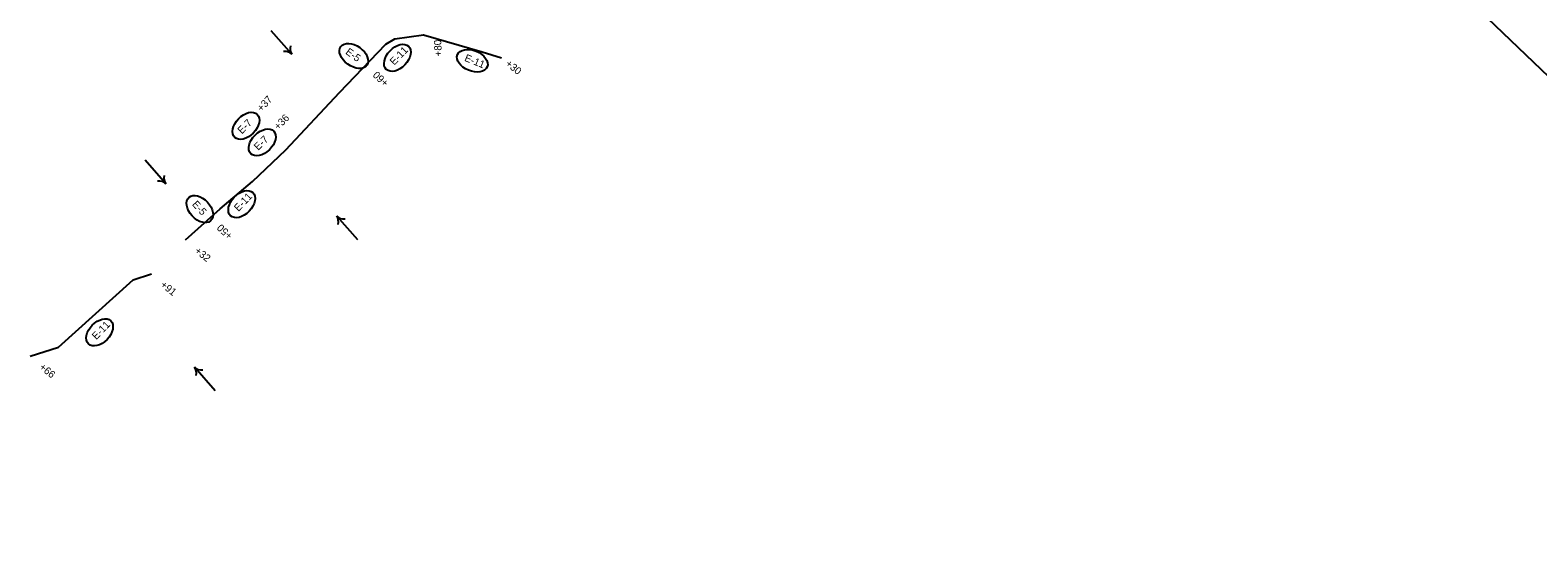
# Model space of a CAD drawing. Extents: x 669236 to 673912, y 735758 to 754788.
# Drawn here: x 671282 to 672567, y 751695 to 752127 of the extents above; entities that cross this region are included whole.
import ezdxf

# ---------------------------------------------------------------- set-up
doc = ezdxf.new("R2010")
doc.units = 0
for name, color, linetype in [('Default', 7, 'Continuous'), ('R_Erosion_3', 7, 'Continuous'), ('R_Flow Arrows', 7, 'Continuous')]:
    doc.layers.add(name, color=color, linetype=linetype)

msp = doc.modelspace()

# ---------------------------------------------------------------- linework, layer by layer
at = {"layer": 'Default'}
msp.add_line((672984.6, 751695), (671992.6, 752646.7), dxfattribs=at)
at = {"layer": 'R_Erosion_3'}
for points in [[(671414.2, 751948.1), (671443.8, 751974.5), (671471.3, 751998), (671499.6, 752025), (671545.4, 752073.8), (671584.9, 752114.9), (671592.5, 752119.5), (671617, 752123), (671666.9, 752108.5), (671683.6, 752103.3)], [(671281.8, 751849), (671306, 751856.7), (671369.6, 751914.1), (671385.1, 751919.2)]]:
    msp.add_lwpolyline(points, dxfattribs=at)
for centre, major_axis in [((671557.6, 752104.9), (11.1, -8)), ((671594.8, 752103.3), (9.49, 9.87)), ((671658.6, 752100.8), (12.7, -5.2)), ((671465.7, 752045.3), (9.54, 9.83)), ((671479.6, 752031.2), (9.78, 9.59)), ((671462.1, 751978.6), (9.49, 9.87)), ((671426.4, 751974.4), (9.2, -10.1)), ((671341, 751869.3), (9.49, 9.87))]:
    msp.add_ellipse(centre, major_axis=major_axis, ratio=0.638788, dxfattribs=at)
at = {"layer": 'R_Flow Arrows'}
for p, q in [((671504.8, 752106.5), (671487.2, 752126.4)), ((671397.3, 751996), (671379.7, 752016)), ((671543.1, 751968.3), (671560.7, 751948.4)), ((671422.1, 751839.6), (671439.6, 751819.7))]:
    msp.add_line(p, q, dxfattribs=at)
for centre, major_axis, start_param, end_param in [((671489.9, 752092.9), (15.1, 13.3), 0.023252, 0.620249), ((671520.2, 752119.5), (-15.1, -13.3), 5.662936, 6.259934), ((671412.7, 752009), (-15.1, -13.3), 5.662936, 6.259934), ((671382.3, 751982.5), (15.1, 13.3), 0.023252, 0.620249), ((671527.7, 751955.3), (15.1, 13.3), 5.662936, 6.259934), ((671558.1, 751981.8), (-15.1, -13.3), 0.023252, 0.620249), ((671406.6, 751826.6), (15.1, 13.3), 5.662936, 6.259934), ((671437, 751853.1), (-15.1, -13.3), 0.023252, 0.620249)]:
    msp.add_ellipse(centre, major_axis=major_axis, ratio=0.5625, start_param=start_param, end_param=end_param, dxfattribs=at)

# ---------------------------------------------------------------- texts
at = {"layer": 'R_Erosion_3'}
for s, rotation, p in [('+80', 92.0322, (671632.6, 752104.6)), ('E-5', 324.3812, (671550, 752107.1)), ('E-11', 46.1169, (671592.1, 752096.6)), ('E-11', 337.7833, (671651.4, 752100.9)), ('+60', 136.5685, (671587.8, 752082.7)), ('+30', 321.2285, (671686.3, 752097.3)), ('+37', 46.976, (671479, 752057)), ('+36', 45.713, (671493.3, 752041.4)), ('E-7', 45.8716, (671462.3, 752038)), ('E-7', 44.449, (671476.1, 752024)), ('E-5', 312.3856, (671419.4, 751978.1)), ('E-11', 46.1169, (671459.3, 751971.9)), ('+50', 136.5685, (671454.9, 751952.4)), ('+32', 321.2285, (671421.4, 751937.8)), ('+91', 321.2285, (671392.3, 751908.9)), ('E-11', 46.1169, (671338.2, 751862.6)), ('+66', 321.2285, (671289, 751838.7))]:
    msp.add_text(s, height=6.25, rotation=rotation, dxfattribs=at).set_placement(p)

doc.saveas('drawing.dxf')
